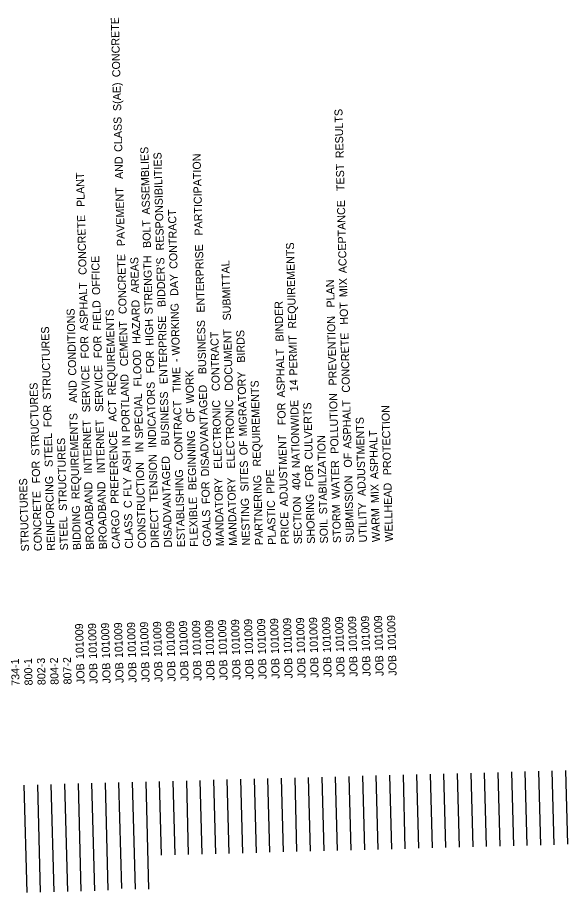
# Model space of a CAD drawing. Extents: x 1929542 to 1931706, y 595440 to 597808.
# Drawn here: x 1931307 to 1931702, y 595447 to 596077 of the extents above; entities that cross this region are included whole.
import ezdxf

# ---------------------------------------------------------------- set-up
doc = ezdxf.new("R2010")
doc.units = 0
doc.layers.add('Default', color=7, linetype='Continuous')

msp = doc.modelspace()

# ---------------------------------------------------------------- linework, layer by layer
at = {"layer": 'Default'}
for p, q in [((1931603.49, 595532.63), (1931604.92, 595479.51)), ((1931613.24, 595532.89), (1931614.66, 595479.78)), ((1931622.98, 595533.16), (1931624.41, 595480.04)), ((1931632.73, 595533.42), (1931634.16, 595480.3)), ((1931642.48, 595533.68), (1931643.9, 595480.56)), ((1931652.22, 595533.94), (1931653.65, 595480.82)), ((1931661.97, 595534.2), (1931663.4, 595481.08)), ((1931671.72, 595534.46), (1931673.14, 595481.35)), ((1931681.46, 595534.72), (1931682.89, 595481.61)), ((1931691.21, 595534.99), (1931692.64, 595481.87)), ((1931700.96, 595535.25), (1931702.38, 595482.13)), ((1931369.57, 595526.35), (1931371.65, 595449.03)), ((1931379.32, 595526.61), (1931381.37, 595450.23)), ((1931389.07, 595526.88), (1931391.14, 595449.81)), ((1931398.81, 595527.14), (1931400.89, 595449.81)), ((1931408.56, 595527.4), (1931409.99, 595474.28)), ((1931418.31, 595527.66), (1931419.73, 595474.54)), ((1931428.05, 595527.92), (1931429.48, 595474.81)), ((1931437.8, 595528.18), (1931439.23, 595475.07)), ((1931447.55, 595528.45), (1931448.97, 595475.33)), ((1931457.29, 595528.71), (1931458.72, 595475.59)), ((1931467.04, 595528.97), (1931468.47, 595475.85)), ((1931476.79, 595529.23), (1931478.21, 595476.11)), ((1931486.53, 595529.49), (1931487.96, 595476.38)), ((1931496.28, 595529.75), (1931497.71, 595476.64)), ((1931506.03, 595530.02), (1931507.45, 595476.9)), ((1931515.77, 595530.28), (1931517.2, 595477.16)), ((1931525.52, 595530.54), (1931526.94, 595477.42)), ((1931535.27, 595530.8), (1931536.69, 595477.68)), ((1931545.01, 595531.06), (1931546.44, 595477.94)), ((1931554.76, 595531.32), (1931556.18, 595478.21)), ((1931564.5, 595531.59), (1931565.93, 595478.47)), ((1931574.25, 595531.85), (1931575.68, 595478.73)), ((1931584, 595532.11), (1931585.42, 595478.99)), ((1931593.74, 595532.37), (1931595.17, 595479.25)), ((1931311.1, 595524.78), (1931313.17, 595447.46)), ((1931320.84, 595525.04), (1931322.92, 595447.72)), ((1931330.59, 595525.31), (1931332.66, 595447.98)), ((1931340.34, 595525.57), (1931342.41, 595448.24)), ((1931350.08, 595525.83), (1931352.16, 595448.51)), ((1931359.83, 595526.09), (1931361.9, 595448.77))]:
    msp.add_line(p, q, dxfattribs=at)

# ---------------------------------------------------------------- texts
for s, p in [(' CONCRETE', (1931380.63, 596032.21)), (' S(AE)', (1931381.28, 596007.84)), (' CLASS', (1931382.07, 595978.46)), (' RESULTS', (1931541.37, 595973.84)), (' ASSEMBLIES', (1931402.01, 595933.32)), (' RESPONSIBILITIES', (1931412.07, 595907.51)), (' AND', (1931382.6, 595958.89)), (' PARTICIPATION', (1931439.87, 595918.19)), (' TEST', (1931542, 595950.26)), (' PLANT', (1931355.04, 595938.82)), (' PAVEMENT', (1931383.89, 595910.62)), (' ACCEPTANCE', (1931543.59, 595891.09)), (' CONTRACT', (1931421.78, 595894.25)), (' CONCRETE', (1931356.36, 595889.91)), (' BOLT', (1931402.65, 595909.27)), (' ENTERPRISE', (1931441.36, 595862.75)), (' REQUIREMENTS', (1931507.21, 595851.23)), (' OFFICE', (1931366.11, 595875.44)), (' CONCRETE', (1931385.2, 595861.71)), (' AREAS', (1931394.17, 595876.64)), (' STRENGTH', (1931403.94, 595861.52)), (" BIDDER'S", (1931413.16, 595866.76)), (' SUBMITTAL', (1931460.23, 595857.11)), (' DAY', (1931422.31, 595874.75)), (' ASPHALT', (1931357.44, 595849.56)), (' PLAN', (1931534.89, 595866.42)), (' MIX', (1931544.05, 595873.92)), (' FIELD', (1931366.8, 595849.81)), (' HAZARD', (1931395.14, 595840.3)), (' BINDER', (1931498.09, 595841.96)), (' CONDITIONS', (1931348.94, 595817.4)), (' REQUIREMENTS', (1931377.41, 595803.22)), (' WORKING', (1931423.46, 595831.98)), (' HOT', (1931544.59, 595854.07)), (' ENTERPRISE', (1931414.65, 595811.32)), (' PREVENTION', (1931536.4, 595810.29)), (' STRUCTURES', (1931330.68, 595800.14)), (' CEMENT', (1931386.21, 595824.17)), (' HIGH', (1931404.54, 595838.92)), (' BUSINESS', (1931442.55, 595818.47)), (' FOR', (1931357.97, 595829.65)), (' FOR', (1931367.33, 595829.9)), (' CONTRACT', (1931452.24, 595806.28)), (' DOCUMENT', (1931461.59, 595806.53)), (' BIRDS', (1931470.41, 595826.72)), (' PERMIT', (1931508.12, 595817.41)), (' CONCRETE', (1931545.9, 595805.16)), (' FLOOD', (1931395.97, 595809.55)), (' FOR', (1931405.08, 595819.02)), (' ASPHALT', (1931499.18, 595801.61)), (' -', (1931423.59, 595827.13)), (' SERVICE', (1931359.01, 595790.98)), (' SERVICE', (1931368.37, 595791.23)), (' TIME', (1931424.17, 595805.23)), (' WORK', (1931433.75, 595797.37)), (' PORTLAND', (1931387.49, 595776.65)), (' MIGRATORY', (1931471.84, 595773.7)), (' 14', (1931508.42, 595806.17)), (' STRUCTURES', (1931322.4, 595759.75)), (' AND', (1931349.47, 595797.82)), (' INDICATORS', (1931406.52, 595765.45)), (' DISADVANTAGED', (1931444.52, 595744.87)), (' REQUIREMENTS', (1931481.78, 595751.96)), (' SPECIAL', (1931396.97, 595772.12)), (' BUSINESS', (1931415.84, 595767.05)), (' POLLUTION', (1931537.72, 595761.15)), (' FOR', (1931331.21, 595780.24)), (' ACT', (1931377.92, 595784.29)), (' CONTRACT', (1931425.48, 595756.51)), (' ELECTRONIC', (1931453.74, 595750.27)), (' ELECTRONIC', (1931463.1, 595750.52)), (' FOR', (1931499.71, 595781.7)), (' NATIONWIDE', (1931509.91, 595750.75)), (' CULVERTS', (1931519.1, 595757.03)), (' ASPHALT', (1931546.98, 595764.81)), (' PROTECTION', (1931575.59, 595745.7)), (' REQUIREMENTS', (1931351.33, 595728.41)), (' OF', (1931434.11, 595783.79)), (' INTERNET', (1931360.2, 595746.91)), (' INTERNET', (1931369.55, 595747.16)), (' ADJUSTMENTS', (1931557.26, 595730.67)), (' PREFERENCE', (1931379.51, 595725.13)), (' BEGINNING', (1931435.42, 595734.96)), (' ASPHALT', (1931566.3, 595742.87)), (' STEEL', (1931331.98, 595751.65)), (' STRUCTURES', (1931342.19, 595720.02)), (' IN', (1931387.76, 595766.63)), (' OF', (1931472.2, 595760.12)), (' ADJUSTMENT', (1931501.28, 595723.2)), (' STABILIZATION', (1931529.52, 595717.59)), (' IN', (1931397.24, 595762.1)), (' ASH', (1931388.26, 595747.74)), (' TENSION', (1931407.56, 595726.55)), ('DISADVANTAGED', (1931417.75, 595695.77)), (' OF', (1931547.35, 595751.23)), (' FOR', (1931322.93, 595739.85)), ('CONSTRUCTION', (1931399.04, 595695.27)), (' SITES', (1931472.9, 595734.01)), (' FOR', (1931519.64, 595737.13)), (' WATER', (1931538.59, 595728.67)), ('REINFORCING', (1931333.54, 595693.51)), ('ESTABLISHING', (1931427.11, 595696.03)), ('PARTNERING', (1931483.25, 595697.53)), (' PIPE', (1931491.67, 595732.38)), (' 404', (1931510.33, 595734.85)), ('SUBMISSION', (1931548.74, 595699.29)), ('STRUCTURES', (1931314.83, 595693.01)), ('BROADBAND', (1931361.61, 595694.27)), ('BROADBAND', (1931370.97, 595694.52)), (' FLY', (1931388.74, 595730.11)), (' FOR', (1931445.06, 595724.97)), ('MANDATORY', (1931455.18, 595696.78)), ('MANDATORY', (1931464.53, 595697.03)), (' MIX', (1931566.76, 595725.7)), ('WELLHEAD', (1931576.81, 595700.04)), ('CONCRETE', (1931324.18, 595693.26)), (' C', (1931388.95, 595722.07)), ('FLEXIBLE', (1931436.46, 595696.28)), ('NESTING', (1931473.89, 595697.28)), ('PLASTIC', (1931492.6, 595697.78)), ('SECTION', (1931511.32, 595698.29)), ('SHORING', (1931520.67, 595698.54)), ('UTILITY', (1931558.1, 595699.54)), ('BIDDING', (1931352.25, 595694.02)), ('CARGO', (1931380.32, 595694.77)), ('DIRECT', (1931408.39, 595695.52)), ('GOALS', (1931445.82, 595696.53)), ('STORM', (1931539.39, 595699.04)), ('WARM', (1931567.45, 595699.79)), ('STEEL', (1931342.9, 595693.77)), ('CLASS', (1931389.68, 595695.02)), ('PRICE', (1931501.96, 595698.04)), ('SOIL', (1931530.03, 595698.79)), (' 101009', (1931550.91, 595618.65)), (' 101009', (1931560.26, 595618.91)), (' 101009', (1931569.62, 595619.16)), (' 101009', (1931578.98, 595619.41)), (' 101009', (1931354.42, 595613.38)), (' 101009', (1931363.77, 595613.63)), (' 101009', (1931373.13, 595613.88)), (' 101009', (1931382.49, 595614.13)), (' 101009', (1931391.84, 595614.39)), (' 101009', (1931401.2, 595614.64)), (' 101009', (1931410.56, 595614.89)), (' 101009', (1931419.91, 595615.14)), (' 101009', (1931429.27, 595615.39)), (' 101009', (1931438.63, 595615.64)), (' 101009', (1931447.98, 595615.89)), (' 101009', (1931457.34, 595616.14)), (' 101009', (1931466.7, 595616.39)), (' 101009', (1931476.05, 595616.65)), (' 101009', (1931485.41, 595616.9)), (' 101009', (1931494.77, 595617.15)), (' 101009', (1931504.12, 595617.4)), (' 101009', (1931513.48, 595617.65)), (' 101009', (1931522.84, 595617.9)), (' 101009', (1931532.19, 595618.15)), (' 101009', (1931541.55, 595618.4)), ('734-1', (1931308.06, 595596.27)), ('800-1', (1931317.42, 595596.52)), ('802-3', (1931326.77, 595596.77)), ('804-2', (1931336.13, 595597.02)), ('807-2', (1931345.49, 595597.28)), ('JOB', (1931448.41, 595600.04)), ('JOB', (1931457.77, 595600.29)), ('JOB', (1931467.12, 595600.54)), ('JOB', (1931476.48, 595600.79)), ('JOB', (1931485.84, 595601.04)), ('JOB', (1931495.19, 595601.29)), ('JOB', (1931504.55, 595601.55)), ('JOB', (1931513.91, 595601.8)), ('JOB', (1931523.26, 595602.05)), ('JOB', (1931532.62, 595602.3)), ('JOB', (1931541.98, 595602.55)), ('JOB', (1931551.33, 595602.8)), ('JOB', (1931560.69, 595603.05)), ('JOB', (1931570.05, 595603.3)), ('JOB', (1931579.4, 595603.55)), ('JOB', (1931354.84, 595597.53)), ('JOB', (1931364.2, 595597.78)), ('JOB', (1931373.56, 595598.03)), ('JOB', (1931382.91, 595598.28)), ('JOB', (1931392.27, 595598.53)), ('JOB', (1931401.63, 595598.78)), ('JOB', (1931410.98, 595599.03)), ('JOB', (1931420.34, 595599.28)), ('JOB', (1931429.7, 595599.54)), ('JOB', (1931439.05, 595599.79))]:
    msp.add_text(s, height=5.76, rotation=91.53769, dxfattribs=at).set_placement(p)

doc.saveas('drawing.dxf')
